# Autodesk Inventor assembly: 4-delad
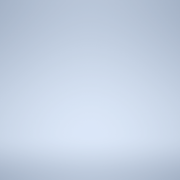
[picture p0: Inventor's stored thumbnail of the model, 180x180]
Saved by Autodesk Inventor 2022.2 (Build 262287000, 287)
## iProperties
RuleStatus: InUse
Created: 2019-06
Part Number: 4-delad
Document SubType Name: Assembly
Designer: cl
Daghöjd: 4000,000 mm
BladBredd: 987,500 mm
Fönsterbredd: 400,000 mm
Fönsterhöjd: 862,000 mm
Brösthöjd: 1000,000 mm
DagBredd: 4000,000 mm
AntalBlad: 4,000 ul
Blad2: 1012,500 mm
Blad3: 0,000 mm
Blad4: 0,000 mm
Blad5: 1012,500 mm
Blad6: 2025,000 mm
MGJ2Djup: 0,000 mm
MGJ2Bredd: 5012,500 mm
MGJ12Djup: 0,000 mm
MGJ12Bredd: 0,000 mm
MGJ56Djup: 0,000 mm
MGJ56Bredd: 0,000 mm
MGJ23Djup: 48,000 mm
MGJ23Bredd: 100,000 mm
MGJ45Djup: 48,000 mm
MGJ45Bredd: 100,000 mm
GarageRegel5: 0,000 mm
GarageRegel6: 0,000 mm
StyrskenaV: 4150,000 mm
Styrrulle2Höjd: 10,000 mm
Styrrulle2Djup: 0,000 mm
FönsterhöjdStyrning: 862,000 mm
BrösthöjdStyrning: 1000,000 mm
FönsterKarm: 54,000 mm
AndraGlasraden: 0,000 mm
BrösthöjdStyrning2: 0,000 mm
InfälldGångDörr: 0,000 ul
Infälldstyr: 845,833 mm
GångjärnHöjd: 2500,000 mm
EnDelGångDörr: 0,000 ul
VinkelJärnStyrSkena: 1456,250 mm
Author: cl
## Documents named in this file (1)
- G:\AutoCad\Carl Lund\3D-modeller systemlösningar\3D-modell-systemlösning-2022\Styrande.iam
## Named parameters: Fönsterhöjd = 862 mm, Blad2 = 1012.5 mm, Blad3 = 0, Blad4 = 0, Blad5 = 1012.5 mm, Blad6 = 2025 mm, MGJ12Djup = 0, MGJ12Bredd = 0, MGJ2Djup = 0, MGJ2Bredd = 5012.5 mm, MGJ56Djup = 0, MGJ56Bredd = 0, MGJ23Djup = 48 mm, MGJ45Djup = 48 mm, GarageRegel5 = 0, GarageRegel6 = 0, Styrrulle2Djup = 0, FönsterhöjdStyrning = 862 mm, FönsterKarm = 54 mm, AndraGlasraden = 0, BrösthöjdStyrning2 = 0.0001 mm, InfälldGångDörr = 0, Infälldstyr = 845.83333 mm, EnDelGångDörr = 0, VinkelJärnStyrSkena = 1456.25 mm
